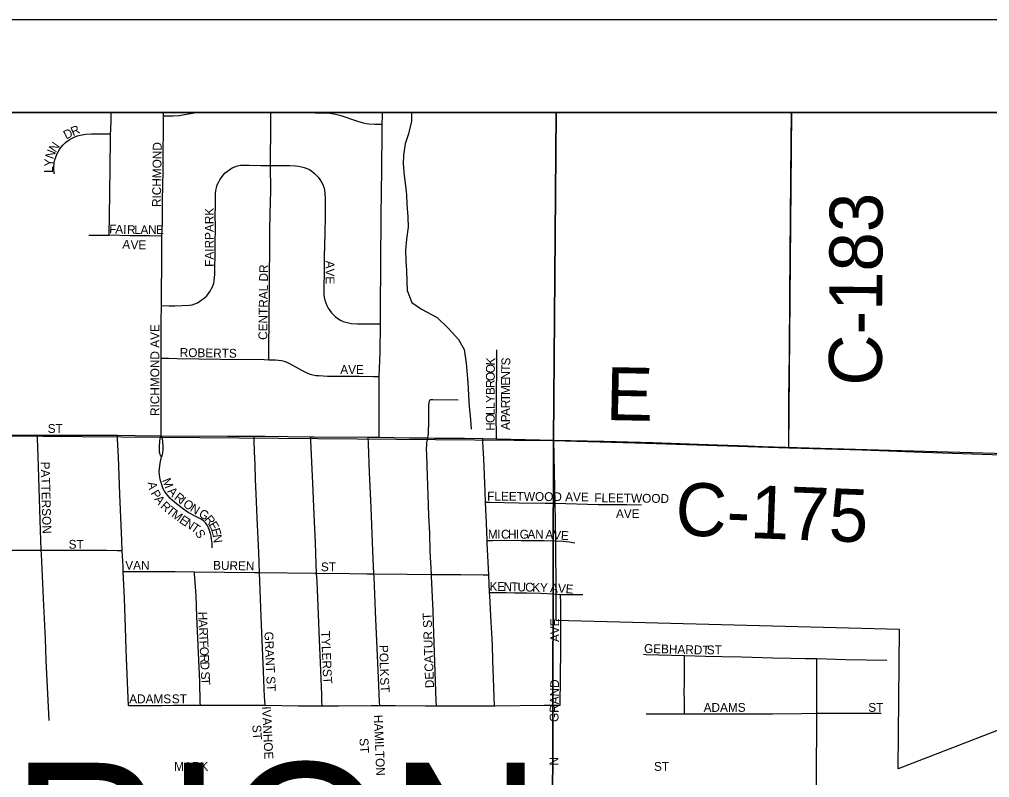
# Model space of a CAD drawing. Extents: x -97 to 34, y -21 to 22.
# Drawn here: x 6.037 to 7.079, y 20.104 to 20.918 of the extents above; entities that cross this region are included whole.
import ezdxf

# ---------------------------------------------------------------- set-up
doc = ezdxf.new("R2010")
doc.units = 0
for name, color, linetype in [('GM_X_City_Street', 7, 'Continuous'), ('GM_X_City_Street_Text', 7, 'Continuous'), ('GM_X_Corporation', 7, 'Continuous'), ('GM_X_County_Road', 7, 'Continuous'), ('GM_X_County_Road_Text', 7, 'Continuous'), ('GM_X_Minor_River', 7, 'Continuous'), ('GM_X_Section', 7, 'Continuous'), ('GM_X_Township', 7, 'Continuous'), ('GM_X_Township_Subdivision', 7, 'Continuous'), ('GM_X_Township_Subdivision_Text', 7, 'Continuous'), ('GM_X_Township_Text', 7, 'Continuous'), ('SH_Data', 7, 'Continuous')]:
    doc.layers.add(name, color=color, linetype=linetype)

msp = doc.modelspace()

# ---------------------------------------------------------------- linework, layer by layer
at = {"layer": 'GM_X_City_Street'}
for points in [[(6.1353, 20.7948), (6.1354, 20.7986), (6.1357, 20.811), (6.1358, 20.8177)], [(6.1921, 20.8142), (6.1992, 20.8143), (6.2024, 20.8143), (6.2087, 20.8148), (6.2272, 20.8177), (6.2278, 20.8177)], [(6.1921, 20.8142), (6.1922, 20.8177)], [(6.307, 20.7611), (6.3069, 20.7714), (6.3073, 20.7962), (6.3073, 20.8118), (6.3073, 20.8177)], [(6.3424, 20.8177), (6.355, 20.8176), (6.3706, 20.8171), (6.3766, 20.8162), (6.3825, 20.8147), (6.4003, 20.8085), (6.4063, 20.8068), (6.4094, 20.8061), (6.4126, 20.8058), (6.419, 20.8055), (6.4269, 20.8052)], [(6.4269, 20.8052), (6.4271, 20.8142), (6.427, 20.8177)], [(6.1904, 20.6851), (6.1908, 20.6995), (6.1909, 20.7117), (6.1911, 20.7239), (6.1912, 20.7392), (6.1916, 20.7555), (6.1917, 20.7647), (6.1917, 20.7763), (6.1919, 20.7971), (6.1921, 20.8082), (6.1921, 20.8142)], [(6.4249, 20.5913), (6.425, 20.6066), (6.4256, 20.7058), (6.426, 20.7337), (6.4263, 20.7553), (6.4267, 20.7987), (6.4269, 20.8052)], [(6.0747, 20.752), (6.0744, 20.7581), (6.0748, 20.7642), (6.0754, 20.7672), (6.0763, 20.7701), (6.0775, 20.773), (6.0788, 20.7757), (6.0804, 20.7783), (6.0822, 20.7808), (6.0843, 20.7831), (6.0865, 20.7852), (6.0888, 20.7872), (6.0914, 20.7889), (6.094, 20.7904), (6.0968, 20.7917), (6.0997, 20.7927), (6.1026, 20.7935), (6.1087, 20.7945), (6.1148, 20.7948), (6.1269, 20.7948), (6.1353, 20.7948)], [(6.1338, 20.6861), (6.1344, 20.7303), (6.1352, 20.7893), (6.1353, 20.7948)], [(6.1899, 20.6108), (6.1978, 20.6106), (6.2041, 20.6104), (6.2196, 20.611), (6.2227, 20.6115), (6.2256, 20.6125), (6.2285, 20.6138), (6.2312, 20.6153), (6.2337, 20.6171), (6.2361, 20.6191), (6.2384, 20.6212), (6.2404, 20.6236), (6.2422, 20.6261), (6.2437, 20.6289), (6.245, 20.6317), (6.2459, 20.6347), (6.2465, 20.6377), (6.2471, 20.6439), (6.2475, 20.672), (6.2478, 20.7), (6.2476, 20.7031), (6.2476, 20.7063), (6.2474, 20.7094), (6.2478, 20.7156), (6.2479, 20.731), (6.2481, 20.7341), (6.2488, 20.7371), (6.2497, 20.7401), (6.251, 20.7429), (6.2525, 20.7456), (6.2543, 20.7482), (6.2562, 20.7507), (6.2583, 20.753), (6.2606, 20.755), (6.2631, 20.7568), (6.2658, 20.7584), (6.2686, 20.7597), (6.2716, 20.7606), (6.2746, 20.7612), (6.2777, 20.7614), (6.284, 20.7615), (6.2964, 20.7611), (6.307, 20.7611)], [(6.305, 20.5527), (6.3051, 20.5617), (6.3052, 20.5741), (6.3055, 20.5865), (6.3056, 20.599), (6.3057, 20.6295), (6.3058, 20.6387), (6.3059, 20.6478), (6.3062, 20.6662), (6.3063, 20.6847), (6.3063, 20.6908), (6.3067, 20.7093), (6.3071, 20.7341), (6.307, 20.7611)], [(6.307, 20.7611), (6.3275, 20.761), (6.3338, 20.7607), (6.3369, 20.7603), (6.34, 20.7597), (6.343, 20.7589), (6.3459, 20.7579), (6.3487, 20.7566), (6.3513, 20.7548), (6.3537, 20.7529), (6.356, 20.7507), (6.358, 20.7484), (6.3599, 20.746), (6.3616, 20.7433), (6.3629, 20.7405), (6.364, 20.7376), (6.3648, 20.7346), (6.3653, 20.7315), (6.3655, 20.7253), (6.3655, 20.716), (6.3654, 20.7098), (6.3655, 20.7067), (6.3652, 20.6881), (6.3646, 20.6632), (6.3645, 20.6507), (6.3642, 20.6259), (6.3643, 20.6228), (6.3646, 20.6197), (6.3652, 20.6167), (6.3661, 20.6137), (6.3673, 20.6108), (6.3687, 20.608), (6.3704, 20.6054), (6.3724, 20.603), (6.3745, 20.6007), (6.3768, 20.5986), (6.3793, 20.5968), (6.382, 20.5952), (6.3848, 20.5938), (6.3877, 20.5928), (6.3907, 20.5921), (6.3938, 20.5916), (6.4001, 20.5913), (6.4156, 20.5911), (6.4187, 20.5912), (6.4249, 20.5913)], [(6.1118, 20.6864), (6.1252, 20.6862), (6.1338, 20.6861)], [(6.1577, 20.6856), (6.1561, 20.6856), (6.1338, 20.6861)], [(6.1904, 20.6851), (6.1773, 20.6855), (6.1577, 20.6856)], [(6.1904, 20.665), (6.1904, 20.6677), (6.1904, 20.6851)], [(6.1899, 20.6108), (6.1899, 20.6153), (6.1904, 20.665)], [(6.1896, 20.5544), (6.1896, 20.5629), (6.1897, 20.5783), (6.1896, 20.5937), (6.1899, 20.6108)], [(6.4236, 20.5347), (6.4247, 20.5603), (6.4249, 20.5913)], [(6.5493, 20.4678), (6.5493, 20.4739), (6.5492, 20.4893), (6.5493, 20.5015), (6.5494, 20.5107), (6.5497, 20.5475), (6.5498, 20.5597), (6.5498, 20.5631)], [(6.1895, 20.471), (6.1895, 20.4761), (6.1896, 20.5078), (6.1897, 20.5456), (6.1896, 20.5544)], [(6.1896, 20.5544), (6.1974, 20.5542), (6.2067, 20.5539), (6.2533, 20.5532), (6.3, 20.5528), (6.305, 20.5527)], [(6.305, 20.5527), (6.3124, 20.5524), (6.3186, 20.5517), (6.3216, 20.551), (6.3245, 20.55), (6.3273, 20.5487), (6.3409, 20.5411), (6.3465, 20.5384), (6.3494, 20.5373), (6.3524, 20.5365), (6.3555, 20.5359), (6.3586, 20.5356), (6.3679, 20.5351), (6.3865, 20.5351), (6.4021, 20.5351), (6.4176, 20.5348), (6.4236, 20.5347)], [(6.4236, 20.4694), (6.4236, 20.4748), (6.4236, 20.495), (6.4235, 20.52), (6.4235, 20.5324), (6.4236, 20.5347)], [(6.4756, 20.4688), (6.4761, 20.4711), (6.4764, 20.4729), (6.4765, 20.4752), (6.4767, 20.485), (6.477, 20.504), (6.4772, 20.5059), (6.4773, 20.5074), (6.4775, 20.5081), (6.4778, 20.5089), (6.478, 20.5093), (6.4783, 20.5096), (6.4787, 20.5098), (6.4797, 20.5099), (6.4812, 20.5099), (6.5082, 20.5096)], [(5.973, 20.4717), (5.994, 20.4717), (6.0529, 20.4717), (6.0567, 20.4717)], [(6.0567, 20.4717), (6.0901, 20.4718), (6.1426, 20.4716)], [(6.0609, 20.3482), (6.0596, 20.3804), (6.0574, 20.4492), (6.0568, 20.4682), (6.0567, 20.4717)], [(6.1426, 20.4716), (6.1615, 20.4715), (6.1895, 20.471)], [(6.1477, 20.3479), (6.1472, 20.3587), (6.1462, 20.3835), (6.1452, 20.4081), (6.1437, 20.4484), (6.1428, 20.4673), (6.1426, 20.4716)], [(6.1899, 20.4483), (6.1894, 20.4491), (6.1888, 20.4501), (6.1885, 20.4509), (6.1882, 20.4518), (6.188, 20.4525), (6.1879, 20.4533), (6.1878, 20.4544), (6.1877, 20.4554), (6.1877, 20.4566), (6.1878, 20.4603), (6.188, 20.4649), (6.1884, 20.468), (6.1888, 20.4696), (6.1895, 20.471)], [(6.1899, 20.4483), (6.1905, 20.4497), (6.191, 20.451), (6.1913, 20.4525), (6.1914, 20.4539), (6.1916, 20.4552), (6.1916, 20.4566), (6.1917, 20.4597), (6.1914, 20.465), (6.1909, 20.4677), (6.1903, 20.4694), (6.1895, 20.471)], [(6.1895, 20.471), (6.2608, 20.4706), (6.2893, 20.4706)], [(6.2952, 20.3244), (6.2943, 20.3459), (6.2925, 20.3832), (6.2914, 20.4089), (6.2909, 20.4243), (6.2903, 20.4397), (6.2897, 20.4542), (6.2894, 20.466), (6.2893, 20.4706)], [(6.2893, 20.4706), (6.3011, 20.4706), (6.3499, 20.4701)], [(6.3564, 20.3238), (6.356, 20.3332), (6.3551, 20.3562), (6.3538, 20.3864), (6.3523, 20.4202), (6.3501, 20.4658), (6.3499, 20.4701)], [(6.3499, 20.4701), (6.3539, 20.4701), (6.4118, 20.4696)], [(6.4178, 20.3229), (6.4166, 20.3477), (6.4148, 20.3942), (6.413, 20.4315), (6.412, 20.4625), (6.4118, 20.4696)], [(6.4118, 20.4696), (6.4128, 20.4695), (6.4236, 20.4694)], [(6.4236, 20.4694), (6.4562, 20.4688), (6.4653, 20.4687), (6.4756, 20.4688)], [(6.4796, 20.3223), (6.4784, 20.3473), (6.4778, 20.3665), (6.477, 20.3851), (6.4761, 20.4078), (6.4755, 20.4277), (6.4747, 20.4503), (6.4744, 20.4573), (6.4746, 20.4611), (6.4748, 20.4634), (6.475, 20.4654), (6.4756, 20.4688)], [(6.4756, 20.4688), (6.4831, 20.4686), (6.5152, 20.4685), (6.5347, 20.4681)], [(6.5347, 20.4681), (6.5493, 20.4678)], [(6.5377, 20.3999), (6.5373, 20.4111), (6.5357, 20.4462), (6.5349, 20.4645), (6.5347, 20.4681)], [(6.5493, 20.4678), (6.611, 20.4665)], [(6.2443, 20.3507), (6.2443, 20.3535), (6.2442, 20.3557), (6.2437, 20.3603), (6.2432, 20.3634), (6.2424, 20.3664), (6.2415, 20.3694), (6.2403, 20.3723), (6.2389, 20.375), (6.2371, 20.3776), (6.2348, 20.3797), (6.2323, 20.3815), (6.2269, 20.3844), (6.2186, 20.3889), (6.2134, 20.3923), (6.206, 20.398), (6.2012, 20.4021), (6.199, 20.4043), (6.1969, 20.4066), (6.1949, 20.409), (6.1931, 20.4116), (6.1916, 20.4143), (6.1905, 20.4172), (6.1887, 20.4232), (6.188, 20.4262), (6.1876, 20.4293), (6.1875, 20.4325), (6.1877, 20.4356), (6.1885, 20.4418), (6.1899, 20.4483)], [(6.5395, 20.3588), (6.5388, 20.3777), (6.538, 20.3924), (6.5377, 20.3999)], [(6.5377, 20.3999), (6.5422, 20.3998), (6.5734, 20.399), (6.6017, 20.3987), (6.6123, 20.3987)], [(6.5395, 20.3588), (6.5455, 20.3588), (6.5577, 20.3589), (6.5761, 20.3587), (6.6008, 20.3587), (6.6131, 20.3585)], [(6.5412, 20.322), (6.5406, 20.3355), (6.5396, 20.3559), (6.5395, 20.3588)], [(5.979, 20.3482), (6.0075, 20.3482), (6.0541, 20.3483), (6.0609, 20.3482)], [(6.0609, 20.3482), (6.0929, 20.3482), (6.1188, 20.3483), (6.1312, 20.3482), (6.1422, 20.348), (6.1477, 20.3479)], [(6.0692, 20.1657), (6.0662, 20.2305), (6.0652, 20.2531), (6.0637, 20.2891), (6.0611, 20.3442), (6.0609, 20.3482)], [(6.1488, 20.3255), (6.1486, 20.3307), (6.1477, 20.3479)], [(6.1488, 20.3255), (6.1538, 20.3255), (6.178, 20.3254), (6.2046, 20.3254), (6.2252, 20.3251)], [(6.1544, 20.1817), (6.1534, 20.2064), (6.1521, 20.2417), (6.1511, 20.2655), (6.15, 20.2966), (6.1488, 20.3255)], [(6.2316, 20.182), (6.2315, 20.1849), (6.2312, 20.2076), (6.2277, 20.2772), (6.227, 20.2997), (6.2254, 20.3228), (6.2252, 20.3251)], [(6.2252, 20.3251), (6.2896, 20.3244), (6.2952, 20.3244)], [(6.301, 20.1821), (6.3007, 20.1875), (6.3005, 20.1906), (6.2992, 20.2185), (6.2973, 20.2682), (6.2956, 20.3149), (6.2952, 20.3244)], [(6.2952, 20.3244), (6.3547, 20.3238), (6.3564, 20.3238)], [(6.3623, 20.1815), (6.3621, 20.1871), (6.3619, 20.1933), (6.3606, 20.2275), (6.3593, 20.2523), (6.3583, 20.2794), (6.357, 20.3147), (6.3564, 20.3238)], [(6.3564, 20.3238), (6.3918, 20.3232), (6.4102, 20.323), (6.4178, 20.3229)], [(6.4242, 20.1817), (6.424, 20.1854), (6.4229, 20.2116), (6.4206, 20.2587), (6.4195, 20.2825), (6.418, 20.3198), (6.4178, 20.3229)], [(6.4178, 20.3229), (6.4536, 20.3225), (6.4796, 20.3223)], [(6.4849, 20.1814), (6.4847, 20.1867), (6.4836, 20.2178), (6.4827, 20.2488), (6.4817, 20.2703), (6.4814, 20.2834), (6.4797, 20.32), (6.4796, 20.3223)], [(6.4796, 20.3223), (6.4938, 20.3222), (6.5112, 20.3223), (6.5351, 20.322), (6.5412, 20.322)], [(6.542, 20.303), (6.5412, 20.322)], [(6.5474, 20.1815), (6.547, 20.1908), (6.5461, 20.2111), (6.5457, 20.23), (6.5452, 20.2465), (6.5444, 20.2598), (6.5436, 20.2712), (6.5422, 20.2993), (6.542, 20.303)], [(6.542, 20.303), (6.5471, 20.303), (6.5599, 20.3029), (6.5688, 20.3027), (6.5819, 20.3025), (6.5972, 20.3021), (6.6102, 20.3015), (6.6182, 20.3009)], [(6.6179, 20.1819), (6.6184, 20.2418), (6.6186, 20.2585), (6.6186, 20.2728)], [(6.7071, 20.2366), (6.7102, 20.2364), (6.7374, 20.2357), (6.7512, 20.2354)], [(6.7512, 20.1726), (6.7511, 20.1869), (6.751, 20.1962), (6.7512, 20.2055), (6.7512, 20.2205), (6.7512, 20.2323), (6.7512, 20.2354)], [(6.7512, 20.2354), (6.7738, 20.2348), (6.7914, 20.2343), (6.8129, 20.2338), (6.8459, 20.2329), (6.8653, 20.2325), (6.8807, 20.2323), (6.8934, 20.2322)], [(6.8932, 20.1734), (6.8932, 20.2081), (6.8933, 20.2286), (6.8934, 20.2322)], [(6.8934, 20.2322), (6.9239, 20.231), (6.9686, 20.2302)], [(6.1544, 20.1817), (6.1625, 20.1817), (6.1811, 20.1817), (6.1904, 20.1818), (6.2028, 20.182), (6.2206, 20.182), (6.2316, 20.182)], [(6.2316, 20.182), (6.2671, 20.1821), (6.2853, 20.1821)], [(6.2853, 20.1821), (6.2991, 20.1822), (6.301, 20.1821)], [(6.301, 20.1821), (6.3364, 20.1815), (6.3623, 20.1815)], [(6.415, 20.1816), (6.4242, 20.1817)], [(6.4242, 20.1817), (6.4263, 20.1817), (6.4407, 20.1817), (6.4732, 20.1814), (6.4849, 20.1814)], [(6.5474, 20.1815), (6.5479, 20.1815), (6.6007, 20.1821), (6.6131, 20.1819), (6.6179, 20.1819)], [(6.3623, 20.1815), (6.38, 20.1815), (6.415, 20.1816)], [(6.4849, 20.1814), (6.5012, 20.1813), (6.5176, 20.1814), (6.5474, 20.1815)], [(6.7101, 20.1726), (6.7365, 20.1726), (6.7512, 20.1726)], [(6.7512, 20.1726), (6.7753, 20.1726), (6.8258, 20.1728), (6.8456, 20.1728), (6.8768, 20.1731), (6.8932, 20.1734)], [(6.893, 20.1092), (6.8929, 20.1239), (6.8932, 20.1498), (6.8932, 20.1617), (6.8932, 20.1734)], [(6.8932, 20.1734), (6.9275, 20.1734), (6.9593, 20.1735), (6.9624, 20.1734)], [(6.8922, 19.912), (6.8922, 19.9217), (6.8923, 19.9324), (6.8923, 19.9405), (6.8923, 19.9504), (6.8923, 19.9574), (6.8923, 19.9665), (6.8923, 19.9749), (6.8925, 19.9839), (6.8925, 20.0035), (6.8928, 20.0194), (6.8928, 20.0295), (6.893, 20.0449), (6.893, 20.0657), (6.8932, 20.0823), (6.893, 20.1092)]]:
    msp.add_lwpolyline(points, dxfattribs=at)
at = {"layer": 'GM_X_Corporation'}
msp.add_line((6.8663, 20.8177), (5.1655, 20.8177), dxfattribs=at)
msp.add_lwpolyline([(7.3656, 20.2626), (6.9807, 20.1139), (6.9819, 20.2632), (6.6136, 20.2728), (6.6134, 20.3013), (6.613, 20.3585), (6.6123, 20.3987), (6.611, 20.4665), (6.8633, 20.4583), (6.8663, 20.8177)], dxfattribs=at)
at = {"layer": 'GM_X_County_Road'}
for points in [[(6.8633, 20.4583), (6.8631, 20.4786), (6.8633, 20.5096), (6.864, 20.5594), (6.8644, 20.6216), (6.8648, 20.6652), (6.8655, 20.746), (6.8658, 20.7865), (6.8661, 20.8177)], [(6.611, 20.4665), (6.629, 20.466)], [(6.629, 20.466), (6.6645, 20.4651), (6.7173, 20.4639), (6.7762, 20.4618), (6.8197, 20.4601), (6.8633, 20.4583)], [(6.8633, 20.4583), (6.9418, 20.4558), (7.007, 20.4535), (7.0816, 20.4511), (7.1127, 20.45), (7.209, 20.4474), (7.2494, 20.4464), (7.2991, 20.4453), (7.3488, 20.4442), (7.368, 20.4437)]]:
    msp.add_lwpolyline(points, dxfattribs=at)
at = {"layer": 'GM_X_Minor_River'}
for points in [[(6.4581, 20.8177), (6.4583, 20.8084), (6.4551, 20.7948), (6.4515, 20.7843), (6.4495, 20.7722), (6.4493, 20.7627), (6.4503, 20.7502), (6.4517, 20.7392), (6.4527, 20.7297), (6.4533, 20.7194), (6.4542, 20.7058), (6.4545, 20.6948), (6.4528, 20.6819), (6.4518, 20.6698), (6.4521, 20.6588), (6.4527, 20.6482), (6.4533, 20.6364), (6.4535, 20.627)], [(6.4535, 20.627), (6.4586, 20.614), (6.4688, 20.607), (6.4857, 20.5981), (6.4976, 20.5866), (6.5085, 20.5743), (6.5147, 20.5636), (6.5168, 20.5488), (6.5188, 20.5283), (6.5194, 20.5146), (6.5203, 20.5025), (6.5217, 20.4884), (6.5223, 20.4782)]]:
    msp.add_lwpolyline(points, dxfattribs=at)
at = {"layer": 'GM_X_Section'}
for p, q in [((6.6134, 20.8177), (5.6017, 20.8177)), ((7.6241, 20.8177), (6.6134, 20.8177))]:
    msp.add_line(p, q, dxfattribs=at)
for points in [[(5.6017, 20.8177), (5.598, 20.4746), (6.6105, 20.4661), (6.6134, 20.8177)], [(6.6134, 20.8177), (6.6105, 20.4661), (7.6199, 20.4372), (7.6241, 20.8177)]]:
    msp.add_lwpolyline(points, dxfattribs=at)
for points in [[(5.598, 20.4746), (6.6105, 20.4661), (6.6081, 19.4622), (5.5961, 19.4736)], [(7.6199, 20.4372), (7.611, 19.4121), (6.6081, 19.4622), (6.6105, 20.4661)]]:
    msp.add_lwpolyline(points, close=True, dxfattribs=at)
at = {"layer": 'GM_X_Township'}
msp.add_lwpolyline([(8.6417, 20.8177), (3.5515, 20.8177), (3.5515, 17.4809)], dxfattribs=at)
at = {"layer": 'GM_X_Township_Subdivision'}
for points in [[(6.6123, 20.3987), (6.6585, 20.3975), (6.6895, 20.3972), (6.705, 20.397)], [(6.6131, 20.3585), (6.6209, 20.3581), (6.6276, 20.3573), (6.6335, 20.3563)], [(6.6186, 20.2728), (6.6186, 20.276), (6.6184, 20.2917), (6.6182, 20.3009)], [(6.6182, 20.3009), (6.6247, 20.3009), (6.6337, 20.3009), (6.6422, 20.3009)]]:
    msp.add_lwpolyline(points, dxfattribs=at)
at = {"layer": 'SH_Data'}
for p, q in [((3.4515, 20.9177), (10.4515, 20.9177)), ((3.5515, 20.8177), (10.3515, 20.8177))]:
    msp.add_line(p, q, dxfattribs=at)

# ---------------------------------------------------------------- texts
at = {"layer": 'GM_X_City_Street_Text'}
for s, rotation, p in [('D', 27.22, (6.0876, 20.7888)), ('R', 23.2177, (6.0949, 20.7925)), ('N', 55.9462, (6.0762, 20.7745)), ('N', 69.7125, (6.0736, 20.7672)), ('RICHMOND', 89.2573, (6.1892, 20.7164)), ('Y', 88.2292, (6.0735, 20.7597)), ('L', 89.6175, (6.0734, 20.7531)), ('FAIRPARK', 90, (6.2459, 20.6523)), ('F', 357.8961, (6.1336, 20.6882)), ('A', 357.9099, (6.1402, 20.688)), ('I', 357.9295, (6.1486, 20.6877)), ('R', 359.1152, (6.1529, 20.6875)), ('L', 359.9457, (6.1606, 20.6874)), ('A', 359.9929, (6.1673, 20.6874)), ('N', 359.9929, (6.1756, 20.6874)), ('E', 359.9956, (6.1839, 20.6874)), ('A', 355.0094, (6.1476, 20.672)), ('V', 358.8893, (6.1566, 20.6713)), ('E', 359.9208, (6.1651, 20.6711)), ('CENTRAL DR', 89.3498, (6.3034, 20.5739)), ('AVE', 270, (6.3661, 20.6589)), ('RICHMOND AVE', 90, (6.1875, 20.4923)), ('ROBERTS', 359.0897, (6.2094, 20.5557)), ('AVE', 0, (6.3818, 20.5374)), ('O', 89.4972, (6.5476, 20.5381)), ('K', 86.3909, (6.5476, 20.5463)), ('T', 88.8253, (6.5639, 20.5397)), ('S', 86.9929, (6.564, 20.5463)), ('O', 89.9928, (6.5476, 20.5298)), ('N', 89.5847, (6.5638, 20.5314)), ('R', 89.9703, (6.5476, 20.5223)), ('E', 89.9727, (6.5638, 20.5248)), ('B', 89.9757, (6.5476, 20.5148)), ('M', 90, (6.5638, 20.5148)), ('T', 90, (6.5638, 20.5081)), ('Y', 89.9928, (6.5476, 20.5064)), ('L', 89.9707, (6.5475, 20.4998)), ('R', 90, (6.5638, 20.5006)), ('L', 89.9727, (6.5475, 20.4931)), ('A', 90, (6.5638, 20.4923)), ('ST', 0, (6.0677, 20.4741)), ('O', 89.9928, (6.5475, 20.4848)), ('H', 89.9781, (6.5475, 20.4764)), ('P', 90, (6.5638, 20.4856)), ('A', 90, (6.5638, 20.4773)), ('PATTERSON', 271.434, (6.0603, 20.4432)), ('M', 291.8927, (6.1903, 20.4234)), ('A', 281.2414, (6.175, 20.4209)), ('P', 300.3556, (6.1778, 20.4095)), ('A', 311.0976, (6.1958, 20.4111)), ('FLEETWOOD AVE', 359.5061, (6.5394, 20.4016)), ('A', 306.4662, (6.1818, 20.4029)), ('R', 317.9101, (6.1881, 20.3946)), ('R', 322.2691, (6.2028, 20.4035)), ('I', 322.125, (6.2087, 20.3989)), ('O', 323.0397, (6.2121, 20.3962)), ('T', 321.0882, (6.1941, 20.3892)), ('M', 323.574, (6.1997, 20.3848)), ('N', 329.532, (6.2197, 20.3906)), ('G', 328.3653, (6.229, 20.3851)), ('E', 326.7527, (6.2082, 20.3785)), ('N', 327.0908, (6.2138, 20.3748)), ('R', 309.0314, (6.2355, 20.3812)), ('E', 300.4905, (6.24, 20.3757)), ('T', 324.999, (6.2207, 20.3703)), ('S', 298.4099, (6.2254, 20.3674)), ('E', 285.2024, (6.2431, 20.3706)), ('M', 359.9818, (6.5402, 20.3607)), ('I', 359.985, (6.5502, 20.3607)), ('C', 359.9757, (6.5543, 20.3607)), ('H', 359.9813, (6.5618, 20.3607)), ('I', 0, (6.5702, 20.3607)), ('G', 359.9781, (6.5743, 20.3607)), ('A', 359.9929, (6.5827, 20.3607)), ('N', 359.7377, (6.591, 20.3607)), ('A', 356.8287, (6.6017, 20.3606)), ('V', 356.3037, (6.61, 20.3601)), ('ST', 0, (6.0902, 20.3499)), ('N', 278.1147, (6.2448, 20.3645)), ('E', 356.3095, (6.6183, 20.3596)), ('VAN', 0, (6.151, 20.3274)), ('BUREN', 358.9938, (6.2452, 20.3274)), ('ST', 0, (6.361, 20.3257)), ('K', 358.6012, (6.5419, 20.3049)), ('E', 358.5795, (6.5502, 20.3047)), ('N', 358.5966, (6.5569, 20.3045)), ('T', 358.5795, (6.5652, 20.3043)), ('U', 358.5966, (6.5719, 20.3042)), ('C', 358.5916, (6.5802, 20.304)), ('K', 358.5966, (6.5877, 20.3038)), ('Y', 358.5794, (6.596, 20.3036)), ('A', 356.9826, (6.6068, 20.3033)), ('V', 355.7991, (6.6151, 20.3029)), ('E', 355.7878, (6.6234, 20.3023)), ('H', 271.224, (6.2294, 20.2822)), ('DECATUR ST', 92.0203, (6.4825, 20.2005)), ('A', 272.4391, (6.2296, 20.2737)), ('AVE', 90, (6.6167, 20.2498)), ('R', 272.5586, (6.23, 20.2653)), ('T', 272.5785, (6.2303, 20.2578)), ('GRANT ST', 272.5247, (6.3003, 20.2607)), ('TYLER', 272.5484, (6.3611, 20.2615)), ('F', 272.5785, (6.2306, 20.2512)), ('O', 272.5859, (6.2309, 20.2445)), ('POLK', 271.5901, (6.4236, 20.2465)), ('GEBHARDT', 358.4932, (6.7077, 20.2382)), ('ST', 0, (6.7752, 20.2366)), ('R', 272.575, (6.2313, 20.2362)), ('D', 272.5579, (6.2316, 20.2287)), ('S', 272.5691, (6.2321, 20.2179)), ('ST', 273.5746, (6.3628, 20.2207)), ('T', 272.5785, (6.2324, 20.2112)), ('ST', 273.8257, (6.4244, 20.2116)), ('GRAND', 89.0478, (6.6159, 20.1639)), ('ADAMS', 0, (6.1552, 20.1841)), ('ST', 0, (6.201, 20.1841)), ('ADAMS', 0, (6.7718, 20.1749)), ('ST', 0, (6.9485, 20.1749)), ('IVANHOE', 272.6964, (6.2978, 20.1806)), ('HAMILTON', 272.3242, (6.4178, 20.1715)), ('ST', 273.5746, (6.2873, 20.1607)), ('ST', 273.5874, (6.4023, 20.1464)), ('MARK', 0, (6.2035, 20.1116)), ('N', 90, (6.6159, 20.1173)), ('ST', 0, (6.7185, 20.1116))]:
    msp.add_text(s, height=0.00947, rotation=rotation, dxfattribs=at).set_placement(p)
at = {"layer": 'GM_X_County_Road_Text'}
for s, height, rotation, p in [('C-183', 0.05682, 89.7253, (6.963, 20.5247)), ('E', 0.0568, 358.8731, (6.6664, 20.488)), ('C-175', 0.05682, 357.7932, (6.7408, 20.3645))]:
    msp.add_text(s, height=height, rotation=rotation, dxfattribs=at).set_placement(p)
at = {"layer": 'GM_X_Township_Subdivision_Text'}
for s, rotation, p in [('FLEETWOOD', 359.3332, (6.6544, 20.3999)), ('AVE', 0, (6.6777, 20.3828))]:
    msp.add_text(s, height=0.00947, rotation=rotation, dxfattribs=at).set_placement(p)
at = {"layer": 'GM_X_Township_Text'}
msp.add_text('CITY OF MARION', height=0.170455, rotation=0, dxfattribs=at).set_placement((4.724, 19.9498))

doc.saveas('drawing.dxf')
